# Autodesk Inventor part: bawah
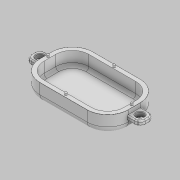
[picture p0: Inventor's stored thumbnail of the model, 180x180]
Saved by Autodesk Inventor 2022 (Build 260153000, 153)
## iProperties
Created: 2022-06
Part Number: bawah
Material: Generic
Document SubType Name: Modeling
Designer: Dragon
Density: 1 g/cm^3
Appearance: Default
Author: Dragon
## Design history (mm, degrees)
sketch "Sketch1"
  geometry: L1 (400, -450)-(-400, -450); L2 (-750, -100)-(-750, 100); L3 (-400, 450)-(400, 450); L4 (750, 100)-(750, -100); L5 (750, -450)-(-750, 450); L6 (-750, -450)-(750, 450); A1 r 350 centre (400, 100) between (750, 100) and (400, 450); A2 r 350 centre (-400, 100) between (-400, 450) and (-750, 100); A3 r 350 centre (-400, -100) between (-750, -100) and (-400, -450); A4 r 350 centre (400, -100) between (400, -450) and (750, -100); 1 further point
  constraints: 12 end point, 8 point on circle, 8 point on line, 8 tangent, 4 centre point, 3 equal radius, 2 midpoint, 2 parallel, 1 horizontal, 1 perpendicular
  dimensions: "d0" = 1500 distance of L5.end L6.end; "d1" = 900 distance of L6.start L5.end; "d2" = 350 radius of A1
extrude "Extrusion1" new body sketch "Sketch1" distance "d3" = 300; taper "d4" = 0 deg
fillet "Fillet1" dims "d5" = 120
shell "Shell1" dims "d6" = 70
chamfer "Chamfer2" distance "d22" = 1; stored, may be unused: second distance "d23" = 1.75, angle "d24" = 45 deg
sketch "Sketch4"
  geometry: L1 (-680, -100)-(-680, 100) reference; L2 (-680, 0)-(-710, 0); L3 (-400, 380)-(400, 380) reference; L4 (0, 380)-(0, 410); C1 r 20 at (-710, 0); C2 r 20 at (0, 410); 1 further point
  constraints: 4 end point, 2 centre point, 2 coincident, 2 midpoint, 1 horizontal, 1 vertical
  dimensions: "d25" = 30 distance of L2.start L2.end; "d26" = 40 diameter of C1; "d27" = 30 distance of L4.start L4.end; "d28" = 40 diameter of C2
extrude "Extrusion4" join sketch "Sketch4" distance "d29" = 30; taper "d30" = 0 deg
mirror "Mirror2"
mirror "Mirror3"
sketch "Sketch6"
  geometry: L1 (-20, 27.796)-(-20, 107.796); L2 (-20, 107.796)-(220, 107.796); L3 (220, 107.796)-(220, 27.796); L4 (220, 27.796)-(-20, 27.796); L5 (-20, 27.796)-(220, 107.796); L6 (-20, 107.796)-(220, 27.796); 2 further points
  constraints: 12 end point, 2 midpoint, 2 parallel, 1 perpendicular, 1 vertical
  dimensions: "d36" = 80 distance of L1.start L1.end; "d37" = 240 distance of L1.end L2.end
extrude "Extrusion6" join sketch "Sketch6" distance "d38" = 220; taper "d39" = 0 deg; dims "d59" = 2, "d60" = 0
chamfer "Chamfer3" distance "d40" = 40; stored, may be unused: second distance "d41" = 70, angle "d42" = 45 deg
chamfer "Chamfer4" distance "d43" = 40; stored, may be unused: second distance "d44" = 70, angle "d45" = 45 deg
fillet "Fillet3" dims "d46" = 80
fillet "Fillet4" dims "d47" = 20
sketch "Sketch7"
  geometry: L1 (0, 0)-(5.5, 0); L2 (0, 5.5)-(0, 0); L3 (0, 0)-(100, 0); L4 (100, 0)-(100, 100); L5 (100, 100)-(0, 100); L6 (0, 100)-(0, 0); C1 r 65 at (100, 100); 3 further points; 1 other entity
  constraints: 12 end point, 2 horizontal, 2 parallel, 1 centre point, 1 coincident, 1 perpendicular, 2 other
  dimensions: "d51" = 100 distance of L5.end L4.end; "d52" = 100 distance of L4.end L3.end; "d53" = 130 diameter of C1
extrude "Extrusion7" cut sketch "Sketch7" distance "d54" = 160; taper "d55" = 0 deg
chamfer "Chamfer5" distance "d56" = 10; stored, may be unused: second distance "d57" = 7, angle "d58" = 45 deg
mirror "Mirror4"
body "Solid1"
